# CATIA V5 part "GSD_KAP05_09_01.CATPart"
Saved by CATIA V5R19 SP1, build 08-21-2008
Part number: GSD_LAW_01
Definition: Beispielmodell für die Funktion Regel / Law.
Description: CATIA V5 Flächenmodellierung  Copyright (c) 2009 Maik Hertha IT Consultants
Bounding box of the stored display mesh (mm): x -76.992 to 62.762, y -20 to 42.193, z 20 to 53.475
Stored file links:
  C:\Users\Maik\CAD Daten\modelle\gsd_buch_uebung\GSD_KAP05_09_01.CATPart
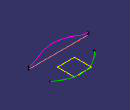
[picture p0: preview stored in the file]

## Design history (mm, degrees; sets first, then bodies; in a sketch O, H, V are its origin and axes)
AxisSystem1 "Absolute Axis System": origin (0, 0, 0), X (1, 0, 0), Y (0, 1, 0), Z (0, 0, 1)
Set1 "Regeldefinition.1"
  Plane1: type Equation, A 0, B 0, C 1, Length 20
  Plane2: type Equation, A 0, B 1, C 0, Length -20
  Point1: type OnPlane, Support Plane2, Direction (-1, 0, 0), H -20, V 10
  Sketch1 on Plane2, origin (20, -20, 10), H (-1, 0, 0), V (0, 0, 1)
    line L1 (-42.762, 18.5929) -> (96.9919, 18.5929)
    point P1 (-42.762, 18.5929)
    point P2 (96.9919, 18.5929)
    spline S1 through (-42.762, 23.5929) (-18.321, 34.6053) (27.1974, 42.0023) (63.9383, 32.4902) (96.9919, 23.5929)
    curve C1
    curve C2
    construction line L2 (96.9919, 8.4141) -> (96.9919, 48.2005)
    construction line L3 (-42.762, 6.2345) -> (-42.762, 46.1945)
    point P7 (-42.762, 23.5929)
    point P8 (96.9919, 23.5929)
    distance P8 L1 = 5
    distance P7 L1 = 5
    horizontal: L1 H
    vertical: L2 V, L3 V
    coincidence: P7 L3, P8 L2, P1 L3, P2 L2
Set2 "Regel anwenden.1"
  Plane3: linked copy from another document
  Sketch2 "Skizze.3" on Plane3, origin (0, 0, 20), H (1, 0, 0), V (0, 1, 0)
    spline S1 through (54.5763, 21.2522) (-4.0386, 42.0125) (-60.1592, 11.0797)
    curve C1
Body1 (main body)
